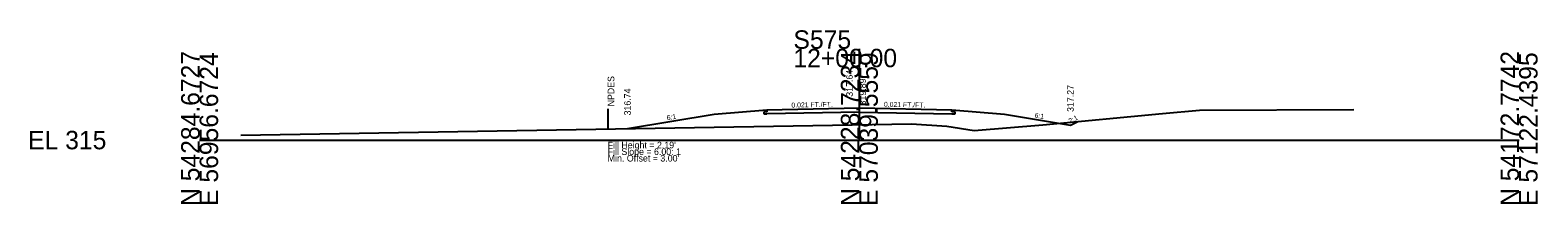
# Model space of a CAD drawing. Extents: x 10119 to 10347, y 94341 to 98867.
# Drawn here: x 10118.6 to 10347.2, y 95841.1 to 95867.5 of the extents above; entities that cross this region are included whole.
import ezdxf

# ---------------------------------------------------------------- set-up
doc = ezdxf.new("R2010")
doc.units = 0
for name, color, linetype in [('Level 10', 7, 'Continuous'), ('Level 11', 7, 'Continuous'), ('Level 12', 7, 'Continuous'), ('Level 32', 7, 'Continuous'), ('Level 33', 7, 'Continuous'), ('Level 50', 7, 'Continuous'), ('Level 55', 7, 'Continuous'), ('Level 59', 7, 'Continuous'), ('Level 6', 7, 'Continuous'), ('Level 60', 7, 'Continuous'), ('Level 63', 7, 'Continuous'), ('Level 7', 7, 'Continuous')]:
    doc.layers.add(name, color=color, linetype=linetype)

msp = doc.modelspace()

# ---------------------------------------------------------------- linework, layer by layer
at = {"layer": 'Level 11'}
for p, q in [((10230.31, 95855.12), (10229.81, 95855.11)), ((10229.81, 95855.11), (10229.81, 95854.77)), ((10229.81, 95854.77), (10230.31, 95854.78)), ((10230.31, 95855.41), (10230.31, 95855.12)), ((10258.31, 95855.12), (10258.31, 95855.41)), ((10258.81, 95855.11), (10258.31, 95855.12)), ((10258.31, 95854.78), (10258.81, 95854.77)), ((10258.81, 95854.77), (10258.81, 95855.11))]:
    msp.add_line(p, q, dxfattribs=at)
at = {"layer": 'Level 12'}
for q in [(10230.31, 95854.78), (10258.31, 95854.78)]:
    msp.add_line((10244.31, 95855.07), q, dxfattribs=at)
at = {"layer": 'Level 55'}
msp.add_line((10206.16, 95855.55), (10206.16, 95852.55), dxfattribs=at)
at = {"layer": 'Level 59'}
for p, q in [((10230.31, 95855.41), (10244.31, 95855.7)), ((10244.31, 95855.7), (10258.31, 95855.41))]:
    msp.add_line(p, q, dxfattribs=at)
at = {"layer": 'Level 6'}
for p, q in [((10222.31, 95854.74), (10230.31, 95855.41)), ((10258.31, 95855.41), (10266.31, 95854.74))]:
    msp.add_line(p, q, dxfattribs=at)
at = {"layer": 'Level 60'}
for p, q in [((10272.1, 95853.13), (10290.28, 95854.83)), ((10290.28, 95854.83), (10295.86, 95855.33)), ((10295.86, 95855.33), (10319.28, 95855.43)), ((10150.57, 95851.56), (10252.2, 95853.28)), ((10252.2, 95853.28), (10257.58, 95852.94)), ((10257.58, 95852.94), (10261.71, 95852.26)), ((10261.71, 95852.26), (10272.1, 95853.13))]:
    msp.add_line(p, q, dxfattribs=at)
at = {"layer": 'Level 63'}
for p, q in [((10244.31, 95850.81), (10244.31, 95864.67)), ((10144.31, 95850.81), (10244.31, 95850.81)), ((10244.31, 95850.81), (10344.31, 95850.81))]:
    msp.add_line(p, q, dxfattribs=at)
at = {"layer": 'Level 7'}
for p, q in [((10209.16, 95852.55), (10222.31, 95854.74)), ((10266.31, 95854.74), (10276.31, 95853.08)), ((10276.31, 95853.08), (10277.41, 95853.62))]:
    msp.add_line(p, q, dxfattribs=at)

# ---------------------------------------------------------------- texts
at = {"layer": 'Level 10'}
msp.add_text('317.64', height=1, rotation=90, dxfattribs=at).set_placement((10243.31, 95857.39))
at = {"layer": 'Level 32'}
for s, rotation, p in [('0.021 FT./FT.', 1.1916, (10234.02, 95855.74)), ('0.021 FT./FT.', 358.8084, (10248.03, 95855.87)), ('6:1', 9.4623, (10215.17, 95853.81)), ('6:1', 350.5377, (10270.83, 95854.24)), ('2:1', 26.5651, (10276.24, 95853.32))]:
    msp.add_text(s, height=0.75, rotation=rotation, dxfattribs=at).set_placement(p)
at = {"layer": 'Level 33'}
for s, p in [('316.74', (10209.66, 95854.55)), ('317.27', (10276.81, 95855.08))]:
    msp.add_text(s, height=1, rotation=90, dxfattribs=at).set_placement(p)
at = {"layer": 'Level 50'}
msp.add_text(' NPDES', height=1, rotation=90, dxfattribs=at).set_placement((10207.16, 95855.55))
for s, p in [("Fill Height = 2.19' ", (10206.16, 95849.55)), ('Fill Slope = 6.00: 1', (10206.16, 95848.55)), ("Min. Offset = 3.00' ", (10206.16, 95847.55))]:
    msp.add_text(s, height=1, dxfattribs=at).set_placement(p)
at = {"layer": 'Level 59'}
msp.add_text(' 319.89', height=1, rotation=90, dxfattribs=at).set_placement((10245.31, 95855.7))
at = {"layer": 'Level 63'}
for s, p in [('S575', (10234.32, 95864.67)), ('12+00.00', (10234.31, 95861.87)), ('EL 315', (10118.31, 95849.41))]:
    msp.add_text(s, height=2.8, dxfattribs=at).set_placement(p)
for s, p in [('N 54284.6727', (10144.31, 95840.81)), ('E 56956.6724', (10147.11, 95840.81)), ('N 54228.7234', (10244.31, 95840.81)), ('E 57039.5559', (10247.11, 95840.81)), ('N 54172.7742', (10344.31, 95840.81)), ('E 57122.4395', (10347.11, 95840.81))]:
    msp.add_text(s, height=2.8, rotation=90, dxfattribs=at).set_placement(p)

doc.saveas('drawing.dxf')
